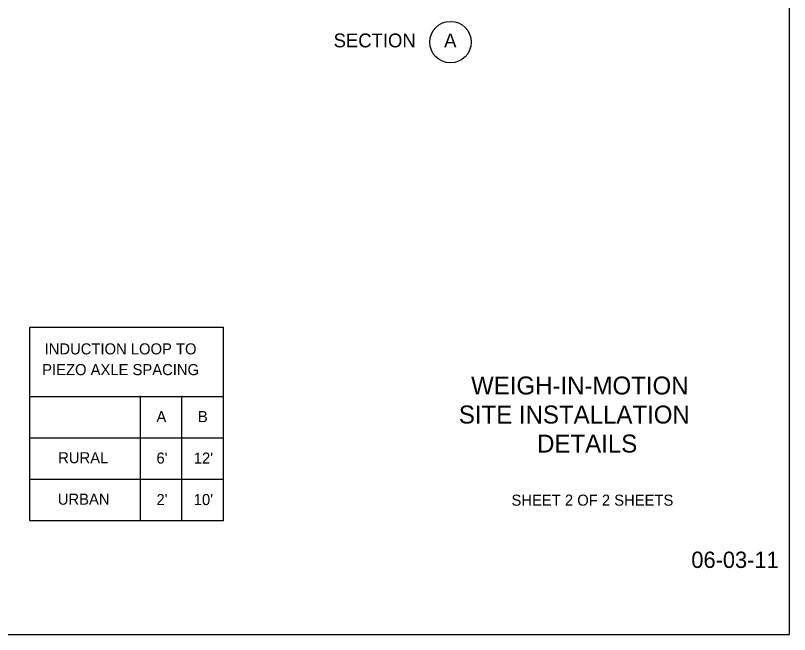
# Model space of a CAD drawing. Extents: x 99862 to 103151, y 100000 to 105076.
# Drawn here: x 102031 to 103151, y 103000 to 103895 of the extents above; entities that cross this region are included whole.
import ezdxf

# ---------------------------------------------------------------- set-up
doc = ezdxf.new("R2010")
doc.units = 0
for name, color, linetype in [('Level 1', 7, 'Continuous'), ('Level 15', 7, 'Continuous'), ('Level 20', 7, 'Continuous'), ('Level 40', 7, 'Continuous'), ('Level 62', 7, 'Continuous'), ('Level 9', 7, 'Continuous')]:
    doc.layers.add(name, color=color, linetype=linetype)

msp = doc.modelspace()

# ---------------------------------------------------------------- linework, layer by layer
at = {"layer": 'Level 1'}
msp.add_lwpolyline([(99862, 102999.5), (103151, 102999.5), (103151, 105075.5), (99862, 105075.5)], close=True, dxfattribs=at)
at = {"layer": 'Level 40'}
for p, q in [((102051.4, 103344.1), (102331.6, 103344.1)), ((102051.4, 103284.1), (102331.6, 103284.1)), ((102051.4, 103224.1), (102331.6, 103224.1))]:
    msp.add_line(p, q, dxfattribs=at)
msp.add_lwpolyline([(102051.4, 103444.1), (102331.4, 103444.1), (102331.4, 103164.1), (102051.4, 103164.1)], close=True, dxfattribs=at)
for points in [[(102271.4, 103164.1), (102211.4, 103164.1), (102211.4, 103345)], [(102331.4, 103164.1), (102271.4, 103164.1), (102271.4, 103345)]]:
    msp.add_lwpolyline(points, dxfattribs=at)
at = {"layer": 'Level 9'}
msp.add_circle((102660.3, 103856.7), 30, dxfattribs=at)

# ---------------------------------------------------------------- texts
at = {"layer": 'Level 15'}
msp.add_text('06-03-11', height=23.62, dxfattribs=at).set_placement((103008.9, 103095.8))
at = {"layer": 'Level 20'}
for s, height, p in [('SECTION', 20, (102491.1, 103849.1)), ('A', 20, (102651.1, 103849.1)), ('INDUCTION LOOP TO', 16, (102072.8, 103404.8)), ('PIEZO AXLE SPACING', 16, (102069.3, 103374.8)), ('A', 16, (102234.7, 103306.8)), ('B', 16, (102294.7, 103306.8)), ('RURAL', 16, (102092.5, 103247.3)), ("6'", 16, (102234.7, 103246.8)), ("12'", 16, (102288.7, 103246.8)), ('URBAN', 16, (102091.9, 103187.3)), ("2'", 16, (102234.7, 103186.8)), ("10'", 16, (102288.7, 103186.8))]:
    msp.add_text(s, height=height, dxfattribs=at).set_placement(p)
at = {"layer": 'Level 62'}
for s, height, p in [('WEIGH-IN-MOTION', 26, (102690.1, 103346.8)), ('SITE INSTALLATION', 26, (102672.4, 103304.8)), ('DETAILS', 26, (102785.7, 103262.8)), ('SHEET 2 OF 2 SHEETS', 16, (102748.6, 103185.9))]:
    msp.add_text(s, height=height, dxfattribs=at).set_placement(p)

doc.saveas('drawing.dxf')
